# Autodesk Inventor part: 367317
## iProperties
Created: 2006-08
Part Number: 367317
Material: 8.8 vz
Description: Senkschraube
Vendor: Autodesk Inc.
Document SubType Name: Modeling
Standard: DIN 7991
Designer: I.Baliuc
Standards Organization: DIN
Language: de-DE
Size Designation: M8 x 35
Categories: <MemberInstance Version="R10.0.0"><Categories><Category DisplayName="Schrauben" InternalName="e4da775c-781d-43d5-af7c-5136215cf5a6" Mnemonic="FSTN"><Category Di
Density: 7.85 g/cm^3
Abmessung: M8 x 35
Author: T.Messerschmitt
Comments: DIN 7991 - M8 x 35
Revision Number: 367317
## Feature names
1. Körper [Revolution]
2. Loch [Extrusion]
3. Fase1 [Chamfer]
